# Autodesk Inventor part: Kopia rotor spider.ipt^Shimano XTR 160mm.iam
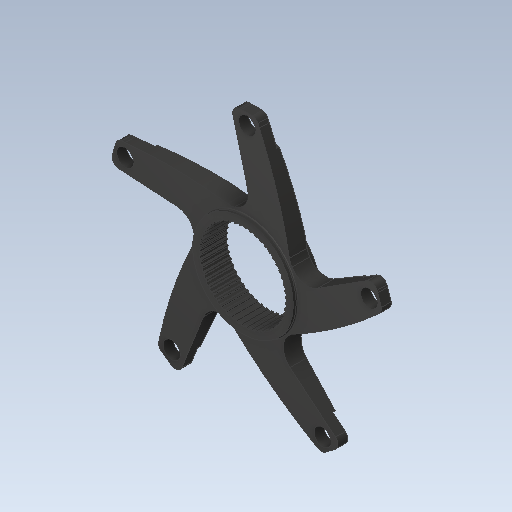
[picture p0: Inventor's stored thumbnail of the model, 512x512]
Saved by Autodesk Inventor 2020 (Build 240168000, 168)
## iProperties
Created: 2017-09
Part Number: Kopia rotor spider.ipt^Shimano XTR 160mm.iam
Material: Ogólny
Document SubType Name: Modeling
Designer: Tomasz
Density: 1 g/cm^3
Appearance: Domyślna
Sending System: SolidWorks 2017
Last Author: Tomasz
Last Saved: 2017-09-11
Author: Tomasz
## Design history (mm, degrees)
feature "rotor spider.ipt"
node "Bryła1"
